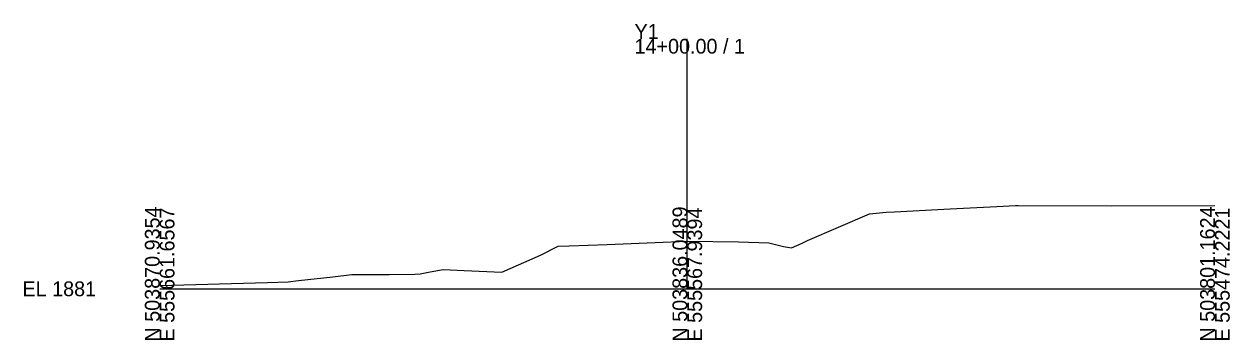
# Model space of a CAD drawing. Extents: x -26 to 203, y -10 to 5015.
# Drawn here: x -25.7 to 202.8, y 3990.3 to 4050.2 of the extents above; entities that cross this region are included whole.
import ezdxf

# ---------------------------------------------------------------- set-up
doc = ezdxf.new("R2010")
doc.units = 0
doc.layers.add('Exist Cross Section Cell', color=7, linetype='Continuous')
doc.layers.add('Exist XS Ground Line', color=7, linetype='Continuous')

msp = doc.modelspace()

# ---------------------------------------------------------------- linework, layer by layer
at = {"layer": 'Exist Cross Section Cell'}
for p, q in [((100, 4000), (100, 4047.4)), ((0, 4000), (100, 4000)), ((100, 4000), (200, 4000))]:
    msp.add_line(p, q, dxfattribs=at)
at = {"layer": 'Exist XS Ground Line'}
for p, q in [((149.8, 4015.17), (158.7, 4015.62)), ((158.7, 4015.62), (162.23, 4015.79)), ((162.23, 4015.79), (162.74, 4015.77)), ((162.74, 4015.77), (180.47, 4015.71)), ((180.47, 4015.71), (200, 4015.8)), ((122.8, 4009.15), (134.56, 4014.23)), ((134.56, 4014.23), (137.68, 4014.5)), ((137.68, 4014.5), (139.29, 4014.58)), ((139.29, 4014.58), (149.8, 4015.17)), ((84.8, 4008.43), (93.94, 4008.79)), ((93.94, 4008.79), (100.04, 4009.02)), ((100.04, 4009.02), (109.73, 4008.88)), ((109.73, 4008.88), (115.48, 4008.74)), ((115.48, 4008.74), (118.26, 4008.04)), ((119.74, 4007.75), (121.76, 4008.63)), ((121.76, 4008.63), (122.8, 4009.15)), ((64.84, 4003.16), (72.21, 4006.4)), ((72.21, 4006.4), (75.55, 4008.07)), ((75.55, 4008.07), (77.59, 4008.12)), ((77.59, 4008.12), (84.8, 4008.43)), ((118.26, 4008.04), (119.74, 4007.75)), ((26.31, 4001.58), (32.85, 4002.26)), ((32.85, 4002.26), (36.42, 4002.7)), ((36.42, 4002.7), (43.48, 4002.71)), ((43.48, 4002.71), (48.38, 4002.79)), ((48.38, 4002.79), (49.38, 4002.85)), ((49.38, 4002.85), (51.28, 4003.24)), ((51.28, 4003.24), (53.75, 4003.67)), ((53.75, 4003.67), (57.73, 4003.47)), ((57.73, 4003.47), (64.84, 4003.16)), ((0, 4000.64), (20.43, 4001.2)), ((20.43, 4001.2), (24.34, 4001.32)), ((24.34, 4001.32), (26.31, 4001.58))]:
    msp.add_line(p, q, dxfattribs=at)

# ---------------------------------------------------------------- texts
at = {"layer": 'Exist Cross Section Cell'}
for s, p in [('Y1', (90, 4047.4)), ('14+00.00 / 1', (90, 4044.6)), ('EL 1881', (-26, 3998.6))]:
    msp.add_text(s, height=2.8, dxfattribs=at).set_placement(p)
for s, p in [('N 503870.9354', (0, 3990)), ('N 503836.0489', (100, 3990)), ('N 503801.1624', (200, 3990)), ('E 555661.6567', (2.8, 3990)), ('E 555567.9394', (102.8, 3990)), ('E 555474.2221', (202.8, 3990))]:
    msp.add_text(s, height=2.8, rotation=90, dxfattribs=at).set_placement(p)

doc.saveas('drawing.dxf')
